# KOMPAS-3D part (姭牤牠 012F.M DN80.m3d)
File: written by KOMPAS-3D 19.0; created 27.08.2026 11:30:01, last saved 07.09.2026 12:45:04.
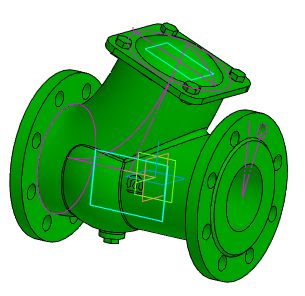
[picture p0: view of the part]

Document properties: Автор: Энергия; Полное имя файла: Z:\3.Личные\kachalov\001_3d для проектировщиков\х.х Тип 012F\012F.M\Клапан 012F.M DN80.m3d

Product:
- Part/product: (unnamed)  | designation Клапан 012F.M DN80
    Масса: 32.6152

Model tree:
1. Эскиз:1
2. Элемент вращения:1
     Угол 1 = 360
3. Эскиз:2  (with: Элемент вращения:1)
4. Перпендикулярная плоскость:1
5. Эскиз:3
6. Эскиз:12  (with: Элемент вращения:1)
7. Элемент по сечениям:1
8. Эскиз:7
9. Элемент выдавливания:2
     Расстояние 2 = 8
10. Эскиз:9  (with: Элемент выдавливания:2)
11. Элемент вращения:2
     Угол 1 = 360
12. Эскиз:10  (with: Элемент вращения:1)
13. Элемент выдавливания:3  (with: Элемент вращения:1)
     Расстояние 2 = 16
14. Массив по концентрической сетке:1  (with: Элемент выдавливания:3, Эскиз:10, Элемент вращения:1)  (8 pattern instances)
     Шаг 2 = 360
15. Эскиз:11  (with: Элемент вращения:1)
16. Элемент выдавливания:4  (with: Элемент вращения:1)
     Расстояние 2 = 16
17. Массив по концентрической сетке:2  (with: Элемент выдавливания:4, Эскиз:11, Элемент вращения:1)  (8 pattern instances)
     Шаг 2 = 360
18. Скругление:6  (with: Элемент выдавливания:2)
     Радиус = 3
19. Эскиз:13  (with: Элемент выдавливания:2)
20. Элемент выдавливания:5  (with: Элемент выдавливания:2)
     Расстояние 1 = 7; Расстояние 2 = 13.5; Смещение 2 = 5.5
21. Массив по концентрической сетке:3  (with: Элемент выдавливания:5, Эскиз:9, Эскиз:13, Элемент вращения:2)  (4 pattern instances)
     Шаг 2 = 360
22. Касательная плоскость:1  (with: Элемент вращения:1)
     Угол = 90
23. Смещенная плоскость:1
     Расстояние = 1
24. Эскиз:14
25. Элемент выдавливания:6  (with: Элемент вращения:1)
     Расстояние 1 = -1.00033; Расстояние 2 = 1
26. Эскиз:15  (with: Элемент вращения:1)
27. Элемент вращения:3  (with: Элемент вращения:1)
     Угол 1 = 360
28. Скругление:10  (with: Элемент вращения:3, Элемент по сечениям:1)
     Радиус = 5
29. Эскиз:16
30. Элемент выдавливания:7
     Расстояние 1 = 80
31. Эскиз:17  (with: Элемент выдавливания:7)
32. Элемент выдавливания:8
     Расстояние 1 = 6.5
33. Эскиз:18  (with: Элемент вращения:1)
34. Элемент выдавливания:9
     Расстояние 2 = 260
35. Скругление:11  (with: Элемент выдавливания:2)
     Радиус = 20
36. Скругление:12  (with: Элемент выдавливания:7)
     Радиус = 3
37. Эскиз:19  (with: Скругление:11, Элемент выдавливания:5)
38. Эскиз:20  (with: Скругление:11)

Expressions: Dn/2; D/2; D2/2; D2/2-5; 360/(2*n); 360/(n*2); D2-6; D2-5; (D2+5)/2
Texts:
  Клапан 012F.M DN80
